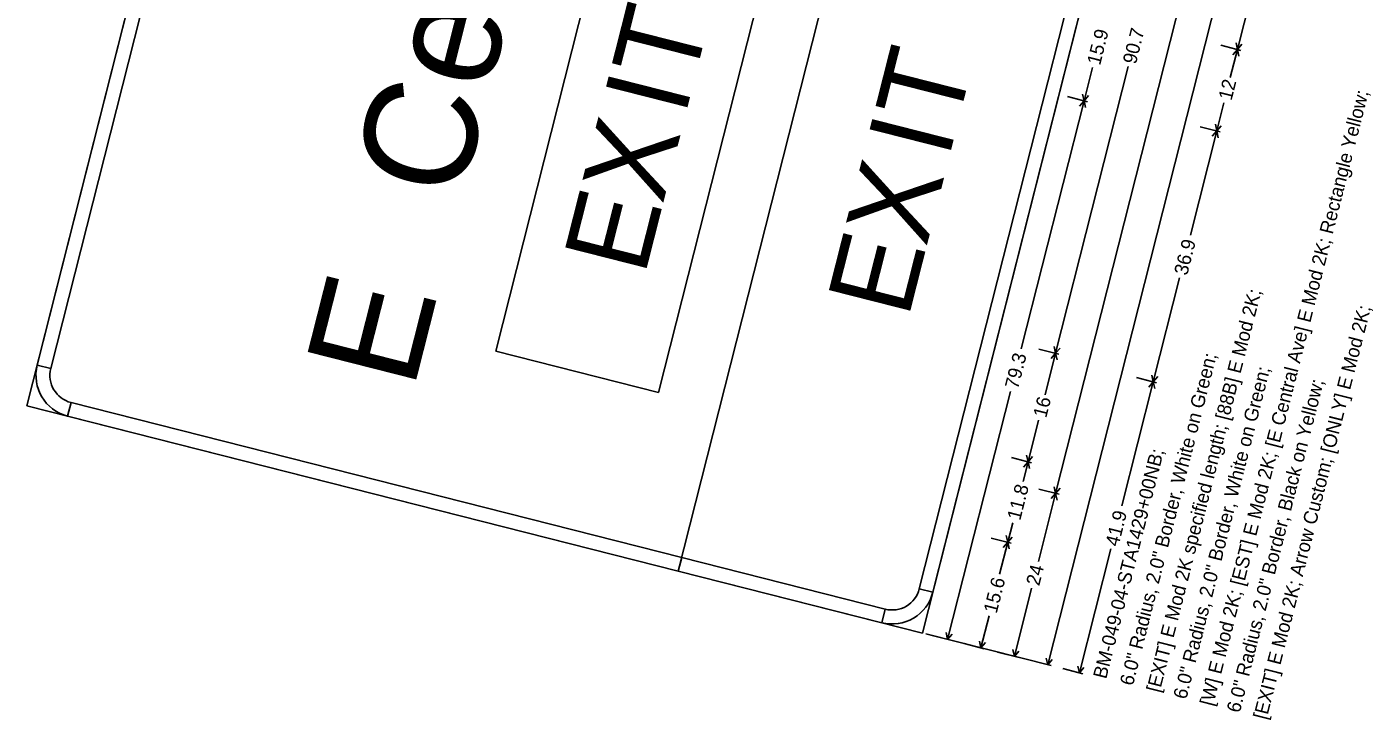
# Model space of a CAD drawing. Extents: x 670003 to 670131, y 737764 to 738002.
# Drawn here: x 670007.41 to 670055.49, y 737847.6 to 737872.34 of the extents above; entities that cross this region are included whole.
import ezdxf

# ---------------------------------------------------------------- set-up
doc = ezdxf.new("R2010")
doc.units = 0
doc.layers.add('R_SIGN', color=7, linetype='Continuous')

msp = doc.modelspace()

# ---------------------------------------------------------------- linework, layer by layer
at = {"layer": 'R_SIGN'}
for p, q in [((670020.318, 737909.703), (670007.411, 737858.814)), ((670030.675, 737852.914), (670043.581, 737903.803)), ((670043.581, 737903.803), (670030.675, 737852.914)), ((670039.399, 737850.702), (670052.305, 737901.59)), ((670024.153, 737860.758), (670034.11, 737900.015)), ((670039.925, 737898.54), (670029.969, 737859.283)), ((670048.969, 737874.674), (670044.153, 737855.686)), ((670050.155, 737874.344), (670043.871, 737849.567)), ((670051.26, 737873.947), (670050.647, 737871.531)), ((670050.595, 737871.772), (670050.647, 737871.531)), ((670050.766, 737871.501), (670050.051, 737871.683)), ((670050.392, 737870.527), (670050.647, 737871.531)), ((670050.487, 737871.345), (670050.647, 737871.531)), ((670050.808, 737871.718), (670050.647, 737871.531)), ((670050.7, 737871.291), (670050.647, 737871.531)), ((670046.748, 737870.921), (670044.153, 737860.689)), ((670045.47, 737870.886), (670045.169, 737869.699)), ((670045.288, 737869.668), (670044.572, 737869.85)), ((670045.116, 737869.939), (670045.169, 737869.699)), ((670045.329, 737869.885), (670045.169, 737869.699)), ((670042.924, 737860.847), (670045.169, 737869.699)), ((670045.008, 737869.512), (670045.169, 737869.699)), ((670045.221, 737869.458), (670045.169, 737869.699)), ((670050.165, 737869.629), (670049.91, 737868.624)), ((670048.967, 737864.905), (670049.91, 737868.624)), ((670050.029, 737868.593), (670049.313, 737868.775)), ((670049.749, 737868.437), (670049.91, 737868.624)), ((670049.857, 737868.864), (670049.91, 737868.624)), ((670050.07, 737868.81), (670049.91, 737868.624)), ((670049.962, 737868.383), (670049.91, 737868.624)), ((670048.581, 737863.386), (670047.638, 737859.667)), ((670029.969, 737859.283), (670024.153, 737860.758)), ((670044.272, 737860.659), (670043.557, 737860.84)), ((670044.1, 737860.93), (670044.153, 737860.689)), ((670044.314, 737860.875), (670044.153, 737860.689)), ((670008.265, 737860.145), (670007.78, 737860.268)), ((670043.776, 737859.205), (670044.153, 737860.689)), ((670043.992, 737860.503), (670044.153, 737860.689)), ((670044.206, 737860.449), (670044.153, 737860.689)), ((670047.757, 737859.637), (670047.042, 737859.818)), ((670047.586, 737859.908), (670047.638, 737859.667)), ((670047.799, 737859.854), (670047.638, 737859.667)), ((670042.538, 737859.327), (670040.293, 737850.475)), ((670046.516, 737855.245), (670047.638, 737859.667)), ((670047.477, 737859.481), (670047.638, 737859.667)), ((670047.691, 737859.427), (670047.638, 737859.667)), ((670007.411, 737858.814), (670030.675, 737852.914)), ((670008.865, 737858.445), (670008.988, 737858.93)), ((670043.546, 737858.297), (670043.17, 737856.812)), ((670043.289, 737856.782), (670042.573, 737856.963)), ((670043.117, 737857.052), (670043.17, 737856.812)), ((670043.33, 737856.998), (670043.17, 737856.812)), ((670042.993, 737856.116), (670043.17, 737856.812)), ((670043.009, 737856.626), (670043.17, 737856.812)), ((670043.222, 737856.572), (670043.17, 737856.812)), ((670044.101, 737855.926), (670044.153, 737855.686)), ((670043.536, 737853.253), (670044.153, 737855.686)), ((670044.273, 737855.655), (670043.557, 737855.837)), ((670043.992, 737855.499), (670044.153, 737855.686)), ((670044.314, 737855.872), (670044.153, 737855.686)), ((670044.206, 737855.445), (670044.153, 737855.686)), ((670042.618, 737854.639), (670042.442, 737853.943)), ((670042.561, 737853.913), (670041.846, 737854.094)), ((670042.389, 737854.183), (670042.442, 737853.943)), ((670042.603, 737854.129), (670042.442, 737853.943)), ((670042.152, 737852.799), (670042.442, 737853.943)), ((670042.281, 737853.757), (670042.442, 737853.943)), ((670042.494, 737853.703), (670042.442, 737853.943)), ((670046.125, 737853.702), (670045.004, 737849.28)), ((670030.675, 737852.914), (670030.675, 737852.914)), ((670030.675, 737852.914), (670039.399, 737850.702)), ((670039.767, 737852.156), (670039.283, 737852.278)), ((670043.295, 737852.303), (670042.678, 737849.87)), ((670038.068, 737851.555), (670037.945, 737851.07)), ((670041.776, 737851.317), (670041.486, 737850.172)), ((670039.399, 737850.702), (670039.399, 737850.702)), ((670043.99, 737849.537), (670039.518, 737850.671)), ((670040.412, 737850.444), (670039.697, 737850.626)), ((670040.241, 737850.715), (670040.293, 737850.475)), ((670040.454, 737850.661), (670040.293, 737850.475)), ((670041.605, 737850.142), (670040.889, 737850.323)), ((670041.433, 737850.413), (670041.486, 737850.172)), ((670041.646, 737850.358), (670041.486, 737850.172)), ((670042.798, 737849.84), (670042.082, 737850.021)), ((670042.626, 737850.11), (670042.678, 737849.87)), ((670042.839, 737850.056), (670042.678, 737849.87)), ((670043.818, 737849.808), (670043.871, 737849.567)), ((670044.032, 737849.754), (670043.871, 737849.567)), ((670045.123, 737849.25), (670044.407, 737849.431)), ((670044.951, 737849.52), (670045.004, 737849.28)), ((670045.164, 737849.466), (670045.004, 737849.28))]:
    msp.add_line(p, q, dxfattribs=at)
for points in [[(670020.434, 737908.126), (670008.265, 737860.145), (670007.78, 737860.268), (670019.949, 737908.249), (670020.434, 737908.126)], [(670039.283, 737852.278), (670051.452, 737900.259), (670051.936, 737900.136), (670039.767, 737852.156), (670039.283, 737852.278)], [(670008.988, 737858.93), (670030.798, 737853.399), (670030.675, 737852.914), (670008.865, 737858.445), (670008.988, 737858.93)], [(670030.798, 737853.399), (670038.068, 737851.555), (670037.945, 737851.07), (670030.675, 737852.914), (670030.798, 737853.399)]]:
    msp.add_lwpolyline(points, close=True, dxfattribs=at)
for centre, radius, start, end in [((670009.234, 737859.899), 1.5, 165.7688, 255.7684), ((670009.234, 737859.899), 1, 165.7688, 255.7684), ((670038.313, 737852.524), 1.5, 255.7684, 345.7686), ((670038.313, 737852.524), 1, 255.7684, 345.7686)]:
    msp.add_arc(centre, radius, start, end, dxfattribs=at)

# ---------------------------------------------------------------- texts
for s, height, p in [('e', 4, (670023.906, 737869.951)), ('T', 3, (670031.194, 737870.215)), ('15.9', 0.4921, (670045.739, 737870.945)), ('90.7', 0.4921, (670047.017, 737870.98)), ('T', 3, (670040.609, 737868.692)), ('C', 4, (670022.922, 737866.074)), ('I', 3, (670030.914, 737869.11)), ('12', 0.4921, (670050.433, 737869.687)), ('[W] E Mod 2K; [EST] E Mod 2K; [E Central Ave] E Mod 2K; Rectangle Yellow; ', 0.49213, (670049.774, 737848.07)), ('X', 3, (670030.117, 737865.969)), ('I', 3, (670040.328, 737867.587)), ('X', 3, (670039.532, 737864.447)), ('E', 3, (670029.468, 737863.41)), ('E', 3, (670038.883, 737861.888)), ('36.9', 0.4921, (670048.85, 737863.444)), ('E', 4, (670021.211, 737859.327)), ('[EXIT] E Mod 2K specified length; [88B] E Mod 2K; ', 0.49213, (670047.866, 737848.554)), ('[EXIT] E Mod 2K; Arrow Custom; [ONLY] E Mod 2K; ', 0.49213, (670051.682, 737847.586)), ('79.3', 0.4921, (670042.807, 737859.385)), ('6.0" Radius, 2.0" Border, White on Green; ', 0.49213, (670046.912, 737848.796)), ('6.0" Radius, 2.0" Border, White on Green; ', 0.49213, (670048.82, 737848.312)), ('6.0" Radius, 2.0" Border, Black on Yellow; ', 0.49213, (670050.728, 737847.828)), ('16', 0.4921, (670043.815, 737858.356)), ('BM-049-04-STA1429+00NB; ', 0.49213, (670045.958, 737849.038)), ('11.8', 0.4921, (670042.887, 737854.698)), ('41.9', 0.4921, (670046.394, 737853.761)), ('24', 0.4921, (670043.564, 737852.361)), ('15.6', 0.4921, (670042.045, 737851.375))]:
    msp.add_text(s, height=height, rotation=75.7686, dxfattribs=at).set_placement(p)

doc.saveas('drawing.dxf')
